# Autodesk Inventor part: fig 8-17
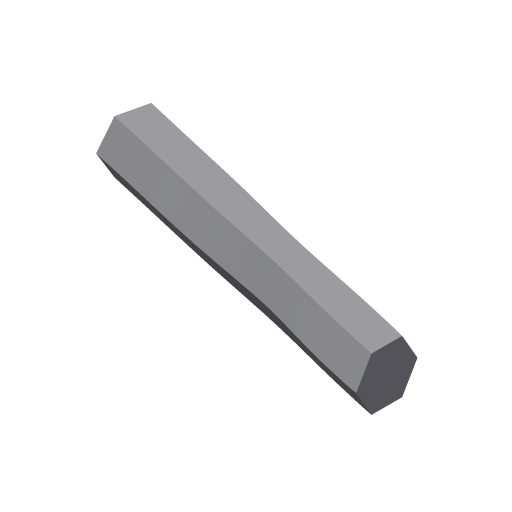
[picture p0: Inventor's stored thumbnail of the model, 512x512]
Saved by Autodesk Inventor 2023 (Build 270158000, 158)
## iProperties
Created: 2004-05
Part Number: fig 8-17
Document SubType Name: Modeling
Designer: CADCIM Technologies
Manufacturer: Standard
Standards Organization: Custom
Density: 1 g/cm^3
Material: Generic
Appearance: Default
Author: CADCIM Technologies
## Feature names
1. Sweep7
## Parameters: d6 = 0, d7 = 0
